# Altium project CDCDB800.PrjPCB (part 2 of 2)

## Sheet CDCDB800_Power.SchDoc: Power
size C; Date: Not shown in title block; ApprovedBy: Not shown in title block; CheckedBy: Not shown in title block; Author: Not shown in title block; CompanyName: Not shown in title block; DrawnBy: Robert Pulatie; Engineer: Not shown in title block; Organization: Not shown in title block; Address1: Not shown in title block; Address2: Not shown in title block; Address3: Not shown in title block; Address4: Not shown in title block; DocumentNumber: 2; Revision: Use project parameter SCH_Rev; SheetNumber: 2; SheetTotal: 6; PageSetup: Record=PageOptions¦CenterHorizontal=True¦CenterVertical=True¦PrintScale=1.00¦XCorrection=1.00¦YCorrection=1.00¦PrintKind=0¦BorderSize=5000000¦LeftOffset=0¦BottomOffset=0¦Orientation=2¦PaperLength=1000¦PaperWidth=1000¦Scale=100¦PaperSource=15¦PrintQuality=600¦MediaType=1¦DitherType=10¦PaperKind=Letter¦PrintScaleMode=1
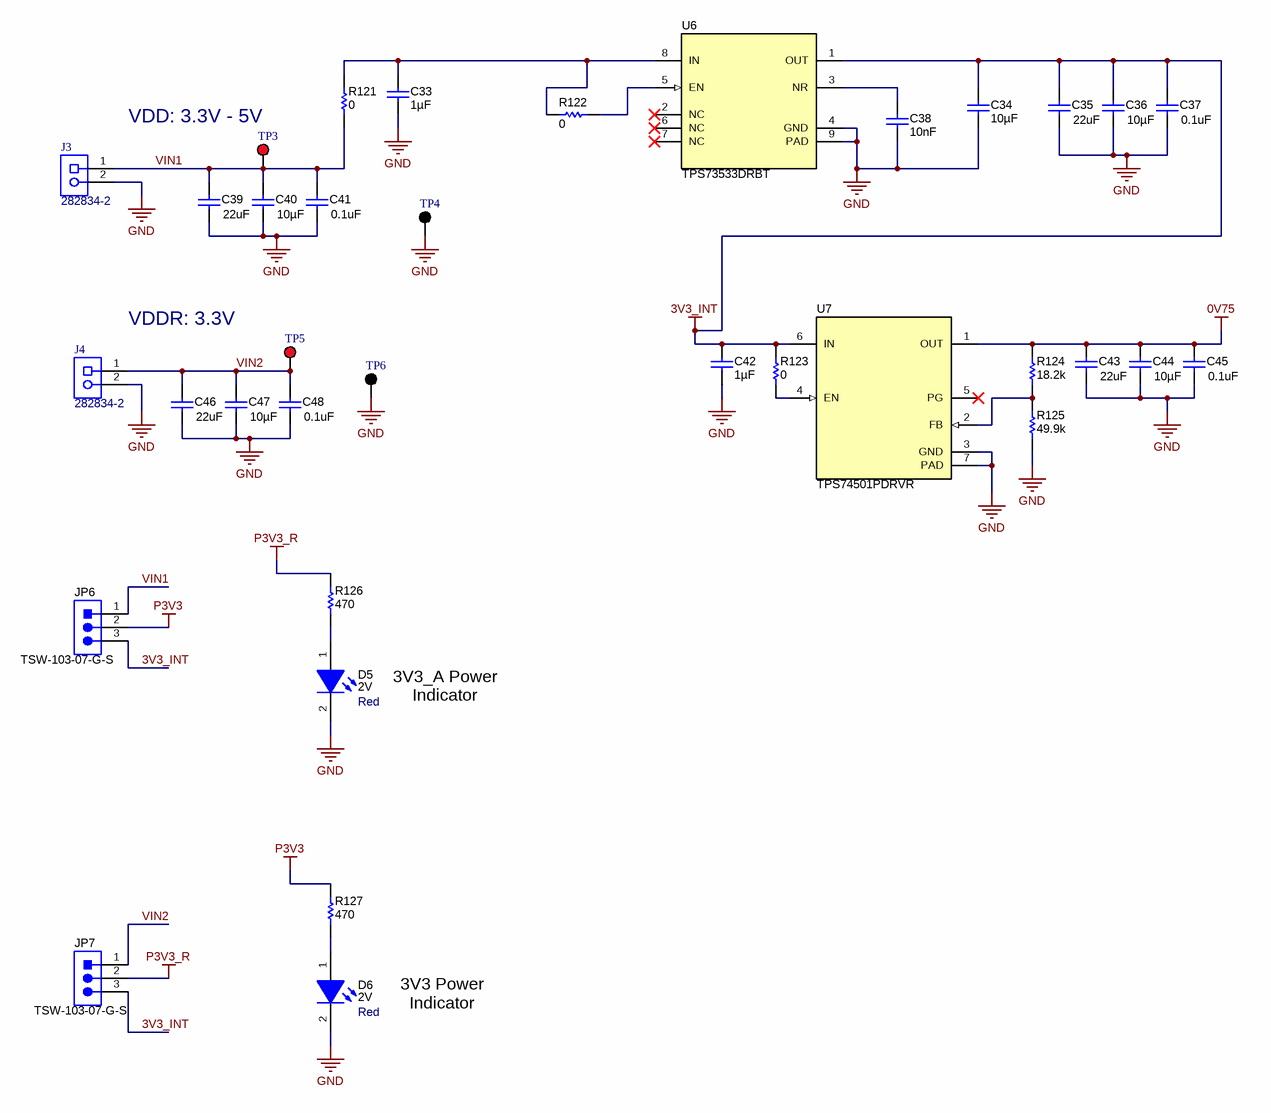
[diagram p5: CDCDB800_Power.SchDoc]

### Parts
C33  Cap_F: 1µF  [0603]  (hidden comment: CGA3E1X7R1V105K080AC)
C34  Cap_F: 10µF  [0603]  (hidden comment: GRM188Z71A106MA73D)
C35  ValueDisplayed: 22uF  [0805_HV]  (hidden comment: LMK212BJ226MG-T)
C36  ValueDisplayed: 10µF  [0603]  (hidden comment: GRM188C81C106MA73D)
C37  ValueDisplayed: 0.1uF  [0402]  (hidden comment: GRM155R71A104KA01D)
C38  Cap_F: 10nF  [0603]  (hidden comment: 0603ZC103KAT2A)
C39  ValueDisplayed: 22uF  [0805_HV]  (hidden comment: LMK212BJ226MG-T)
C40  ValueDisplayed: 10µF  [0603]  (hidden comment: GRM188C81C106MA73D)
C41  ValueDisplayed: 0.1uF  [0402]  (hidden comment: GRM155R71A104KA01D)
C42  Cap_F: 1µF  [0603]  (hidden comment: CGA3E1X7R1V105K080AC)
C43  ValueDisplayed: 22uF  [0805_HV]  (hidden comment: LMK212BJ226MG-T)
C44  ValueDisplayed: 10µF  [0603]  (hidden comment: GRM188C81C106MA73D)
C45  ValueDisplayed: 0.1uF  [0402]  (hidden comment: GRM155R71A104KA01D)
C46  ValueDisplayed: 22uF  [0805_HV]  (hidden comment: LMK212BJ226MG-T)
C47  ValueDisplayed: 10µF  [0603]  (hidden comment: GRM188C81C106MA73D)
C48  ValueDisplayed: 0.1uF  [0402]  (hidden comment: GRM155R71A104KA01D)
D5  value Red  Value2: 2V  [LED_LTST-C170_Red]  (hidden comment: LTST-C170KRKT)
D6  value Red  Value2: 2V  [LED_LTST-C170_Red]  (hidden comment: LTST-C170KRKT)
J3  282834-2  [TEC_282834-2]
J4  282834-2  [TEC_282834-2]
JP6  TSW-103-07-G-S  [TSW-103-07-G-S]
JP7  TSW-103-07-G-S  [TSW-103-07-G-S]
R121  ValueDisplayed: 0  [0603]  (hidden comment: MCT06030Z0000ZP500)
R122  ValueDisplayed: 0  [0603]  (hidden comment: MCT06030Z0000ZP500)
R123  ValueDisplayed: 0  [0603]  (hidden comment: MCT06030Z0000ZP500)
R124  ValueDisplayed: 18.2k  [0402]  (hidden comment: CRCW040218K2FKED)
R125  ValueDisplayed: 49.9k  [0402]  (hidden comment: CRCW040249K9FKED)
R126  ValueDisplayed: 470  [0603]  (hidden comment: CRCW0603470RJNEA)
R127  ValueDisplayed: 470  [0603]  (hidden comment: CRCW0603470RJNEA)
TP3  5010  [Keystone5010]  (value not drawn)
TP4  5011  [Keystone5011]  (value not drawn)
TP5  5010  [Keystone5010]  (value not drawn)
TP6  5011  [Keystone5011]  (value not drawn)
U6  TPS73533DRBT  [DRB0008A]
U7  TPS74501PDRVR  [DRV0006A]

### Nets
0V75: C43.1 C44.1 C45.1 R124.2 U7.1(OUT)
3V3_INT: C34.1 C35.1 C36.1 C37.1 C42.1 JP6.3 JP7.3 R123.1 U6.1(OUT) U7.6(IN)
GND: C33.2 C34.2 C35.2 C36.2 C37.2 C38.2 C39.2 C40.2 C41.2 C42.2 C43.2 C44.2 C45.2 C46.2 C47.2 C48.2 D5.2(K) D6.2(K) J3.2 J4.2 R125.1 TP4.1 TP6.1 U6.4(GND) U6.9(PAD) U7.3(GND) U7.7(PAD)
P3V3: JP6.2 R127.2
P3V3_R: JP7.2 R126.2
VIN1: C39.1 C40.1 C41.1 J3.1 JP6.1 R121.2 TP3.1
VIN2: C46.1 C47.1 C48.1 J4.1 JP7.1 TP5.1
NetC33_1: C33.1 R121.1 R122.1 U6.8(IN)
NetC38_1: C38.1 U6.3(NR)
NetD5_1: D5.1(A) R126.1
NetD6_1: D6.1(A) R127.1
NetR122_2: R122.2 U6.5(EN)
NetR123_2: R123.2 U7.4(EN)
NetR124_1: R124.1 R125.2 U7.2(FB)

Not connected (* = marked no-connect by the designer): U6 2(NC)* 6(NC)* 7(NC)*; U7 5(PG)*

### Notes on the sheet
- (near TP3) VDD: 3.3V - 5V
- VDDR: 3.3V
- 3V3_A Power Indicator
- 3V3 Power Indicator

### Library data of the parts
C33 C42 = CMP-0007067-4: CAP, CERM, 1 uF, 35 V, +/- 10%, X7R, AEC-Q200 Grade 1, 0603; Manufacturer: TDK; TaMin_C: -55°C; ESR_ohm: 5.522m; Polarized: N; SizeAreaWB_mm2: 4.68; Value1: 0.005522 ohm; U/M: EA; Value: 1uF; TaMax_C: 125°C; SizeZ_mm: 1; SizeX_mm: 1.6; SizeY_mm: 0.8; Value2: 35V; SizeArea_mm2: 1.28; AEC Qualified: Y; IRMS_A: 2.21617A; AEC Category: Q200
C34 = CMP-0007497-5: CAP, CERM, 10 uF, 10 V, +/- 20%, X7R, 0603; Manufacturer: MuRata; TaMin_C: -55°C; Polarized: N; SizeAreaWB_mm2: 4.68; Value1: Unknown; U/M: EA; Value: 10uF; TaMax_C: 125°C; SizeZ_mm: 1; SizeX_mm: 1.6; SizeY_mm: 0.8; Value2: 10V; SizeArea_mm2: 1.28; AEC Category: Q200
C35 C39 C43 C46 = CMP-0008403-2: CAP, CERM, 22 uF, 10 V, +/- 20%, X5R, 0805; Manufacturer: Taiyo Yuden; TaMin_C: -55°C; Polarized: N; SizeAreaWB_mm2: 6.75; Value1: Unknown; U/M: EA; Value: 22uF; TaMax_C: 85°C; SizeZ_mm: 1.45; SizeX_mm: 2; SizeY_mm: 1.25; Cap_Case: 0805; Value2: 10V; SizeArea_mm2: 2.5; Cap_F: 22µF; AEC Category: Q200
C36 C40 C44 C47 = CMP-0086062-1: CAP, CERM, 10 µF, 16 V,+/- 20%, X6S, 0603; Manufacturer: MuRata; U/M: EA; AEC Category: Q200; VDC_V: 16V; SizeX_mm: 1.6; SizeY_mm: 0.8; SizeZ_mm: 1; Value: 10uF; SizeArea_mm2: 1.28; TaMin_C: -55°C; Polarized: N; SizeAreaWB_mm2: 4.68; TaMax_C: 105°C
C37 C41 C45 C48 = CMP-0006629-2: CAP, CERM, 0.1 uF, 10 V, +/- 10%, X7R, 0402; Manufacturer: MuRata; TaMin_C: -55°C; Polarized: N; SizeAreaWB_mm2: 3; Value1: Unknown; U/M: EA; Value: 0.1uF; TaMax_C: 125°C; SizeZ_mm: 0.6; SizeX_mm: 1; SizeY_mm: 0.5; Value2: 10V; Cap_F: 100nF; AEC Category: Q200
C38 = CMP-0006814-5: CAP, CERM, 0.01 uF, 10 V, +/- 10%, X7R, 0603; Manufacturer: AVX; TaMin_C: -55°C; Polarized: N; SizeAreaWB_mm2: 4.68; Value1: Unknown; U/M: EA; Value: 0.01uF; TaMax_C: 125°C; SizeZ_mm: 1; SizeX_mm: 1.6; SizeY_mm: 0.8; Value2: 10V; SizeArea_mm2: 1.28; AEC Category: Q200
D5 D6 = CMP-0002829-3: LED, Red, SMD; Manufacturer: Lite-On; SizeZ_mm: 1.2; Value1: W; SizeY_mm: 1.25; SizeArea_mm2: 2.5; SizeX_mm: 2; SizeAreaWB_mm2: 6.75; Io_A: 20mA; Type: AlInGaP
J3 J4 = CMP-0054974-1: Terminal Block, 2x1, 2.54mm, TH; Manufacturer: TE Connectivity; CNHeader: FALSE; Green_Lifecycle: Active; Green_REACh: Passed; CT: TRUE
JP6 JP7 = CMP-0075407-2: Header, 100mil, 3x1, Gold, TH; Manufacturer: Samtec; Cert_CSA: Y; Cert_CULUS: N; Current_A: 6.3A; Gender: Male; Green_Lifecycle: Active; Green_REACh: Passed; Pitch_mm: 2.54; Row_Count: 1; Voltage_V: 550V
R121-R123 = CMP-0025884-3: RES, 0, 5%, 0.125 W, 0603; Manufacturer: Vishay/Beyschlag; Power_W: 125mW; TempCo: ppm/C; Value_Code: 0000; U/M: EA; Value: 0; EIA_Code: E24; SizeX_mm: 1.6; SizeY_mm: 0.8; SizeZ_mm: 1; Value2: 0.125W; SizeArea_mm2: 1.28; AEC Qualified: N; AEC Category: Q200
R124 = CMP-0026059-3: RES, 18.2 k, 1%, 0.063 W, AEC-Q200 Grade 0, 0402; Manufacturer: Vishay-Dale; Power_W: 63mW; TempCo: 100 ppm/C; Value_Code: 18k2; Value: 18.2k; EIA_Code: E96; SizeX_mm: 1; SizeY_mm: 0.5; SizeZ_mm: 0.6; Value2: 0.063W; AEC Qualified: Y; VDC_V: 50V; AEC Category: Q200; AEC Grade: 0
R125 = CMP-0026403-2: RES, 49.9 k, 1%, 0.063 W, AEC-Q200 Grade 0, 0402; Manufacturer: Vishay-Dale; Power_W: 63mW; TempCo: 100 ppm/C; Value_Code: 49k9; Value: 49.9k; EIA_Code: E96; SizeX_mm: 1; SizeY_mm: 0.5; SizeZ_mm: 0.6; Value2: 0.063W; AEC Qualified: Y; VDC_V: 50V; AEC Category: Q200; AEC Grade: 0
R126 R127 = CMP-0025813-4: RES, 470, 5%, 0.1 W, AEC-Q200 Grade 0, 0603; Manufacturer: Vishay-Dale; Power_W: 100mW; TempCo: 200 ppm/C; Value_Code: 470R; Value: 470; EIA_Code: E24; SizeX_mm: 1.6; SizeY_mm: 0.8; SizeZ_mm: 1; Value2: 0.1W; SizeArea_mm2: 1.28; AEC Qualified: Y; VDC_V: 75V; AEC Category: Q200; AEC Grade: 0
TP3 TP5 = CMP-0055147-1: Test Point, Multipurpose, Red, TH; Manufacturer: Keystone; CNHeader: FALSE; Green_Lifecycle: Active; Green_REACh: Passed; ContactFinish: Silver; CT: TRUE
TP4 TP6 = CMP-0055148-1: Test Point, Multipurpose, Black, TH; Manufacturer: Keystone; CNHeader: FALSE; Green_Lifecycle: Active; Green_REACh: Passed; ContactFinish: Silver; CT: TRUE
U6 = CMP-0036329-3: 500mA, Adjustable, Low Quiescent Current, Low-Noise, High-PSRR, Single-Output LDO Regulator, DRB0008A (VSON-8); Manufacturer: Texas Instruments; AEC Category: Q200; Vout Adj(Max)(V): 3.3; Vdo(Typ)(mV): 280; SizeY_mm: 3.0; Vin(Max)(V): 6.5; Accuracy(%): 2; Vin(Min)(V): 2.7; SizeAreaWB_mm2: 16.0; SizeZ_mm: 1.0; AEC Qualified: N; SizeArea_mm2: 9.0; Iout(Max)(A): 0.5; Rating: Catalog; Iq(Typ)(mA): 0.04; CompType: IC
U7 = CMP-0082614-1: 500-mA LDO With Power-Good, DRV0006A (WSON-6); Alternate PartNumber: TPS74501PDRVT; Alternate Manufacturer: Texas Instruments; SizeAreaWB_mm2: 9; SizeZ_mm: 0.8; SizeX_mm: 2; SizeArea_mm2: 4; CompType: IC; AEC Qualified: N; AEC Category: Q200

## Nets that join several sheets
0V75: CDCDB800_Output (16 pins), CDCDB800_Power (5 pins)
GND: CDCDB800_Control (39 pins), CDCDB800_Main (31 pins), CDCDB800_Output (80 pins), CDCDB800_Power (27 pins)
P3V3: CDCDB800_Main (14 pins), CDCDB800_Power (JP6.2 R127.2)
P3V3_R: CDCDB800_Main (L2.1), CDCDB800_Power (JP7.2 R126.2)
CK0_N: CDCDB800_Main (U1.14), CDCDB800_Output (R79.1 R83.1)
CK0_P: CDCDB800_Main (U1.13), CDCDB800_Output (R73.1 R75.1)
CK1_N: CDCDB800_Main (U1.17), CDCDB800_Output (R91.1 R95.1)
CK1_P: CDCDB800_Main (U1.16), CDCDB800_Output (R85.1 R87.1)
CK2_N: CDCDB800_Main (U1.22), CDCDB800_Output (R103.1 R107.1)
CK2_P: CDCDB800_Main (U1.21), CDCDB800_Output (R97.1 R99.1)
CK3_N: CDCDB800_Main (U1.26), CDCDB800_Output (R115.1 R119.1)
CK3_P: CDCDB800_Main (U1.25), CDCDB800_Output (R109.1 R111.1)
CK4_N: CDCDB800_Main (U1.29), CDCDB800_Output (R80.1 R84.1)
CK4_P: CDCDB800_Main (U1.28), CDCDB800_Output (R74.1 R76.1)
CK5_N: CDCDB800_Main (U1.33), CDCDB800_Output (R92.1 R96.1)
CK5_P: CDCDB800_Main (U1.32), CDCDB800_Output (R86.1 R88.1)
CK6_N: CDCDB800_Main (U1.36), CDCDB800_Output (R105.1 R108.1)
CK6_P: CDCDB800_Main (U1.35), CDCDB800_Output (R98.1 R100.1)
CK7_N: CDCDB800_Main (U1.40), CDCDB800_Output (R116.1 R120.1)
CK7_P: CDCDB800_Main (U1.39), CDCDB800_Output (R110.1 R112.1)
GPIO2: CDCDB800_Control (J6.13 R64.2), CDCDB800_Main (R39.1)
GPIO3: CDCDB800_Control (J6.14 R61.2), CDCDB800_Main (R37.1)
GPIO4: CDCDB800_Control (J6.17 R67.2), CDCDB800_Main (R41.1)
GPIO5: CDCDB800_Control (J6.18 R68.2), CDCDB800_Main (R43.1)
GPIO6: CDCDB800_Control (J6.19 R59.2), CDCDB800_Main (R35.1)
GPIO7: CDCDB800_Control (J6.20 R60.1), CDCDB800_Main (R32.1)
GPIO8: CDCDB800_Control (J6.5 R70.2), CDCDB800_Main (R47.1)
GPIO9: CDCDB800_Control (J6.6 R69.2), CDCDB800_Main (R45.1)
GPIO12: CDCDB800_Control (J6.29 R58.1), CDCDB800_Main (R27.1 R31.1)
SCL: CDCDB800_Control (J6.12 R54.1 R63.1 R66.2), CDCDB800_Main (R21.1)
SDA: CDCDB800_Control (J6.11 R62.1 R65.2), CDCDB800_Main (R22.1)

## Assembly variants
001: not fitted C7 C8 C13 C14 C24 C42 C43 C44 C45 C46 C47 C48 FID1 FID2 FID3 FID4 FID5 FID6 J11 J12 J13 J14 J15 J16 J17 J18 J19 J20 J21 J22 JP1 JP2 JP3 R8 R9 R12 R13 R14 R15 R16 R17 R20 R23 R25 R29 R57 R72 R73 R74 R77 R78 R79 R80 R81 R82 R85 R86 R87 R88 R89 R90 R91 R92 R93 R94 R95 R96 R97 R98 R99 R100 R101 R102 R103 R104 R105 R106 R107 R108 R109 R110 R111 R112 R113 R114 R115 R116 R117 R118 R119 R120 R124 R125 U7; alternate parts R75 -> CMP-0027008-4, R83 -> CMP-0027008-4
